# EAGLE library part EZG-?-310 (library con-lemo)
LEMO Connector Source: http://www.lemo.com/pdfs/catalog/ROW/German/unipole_multipole.pdf
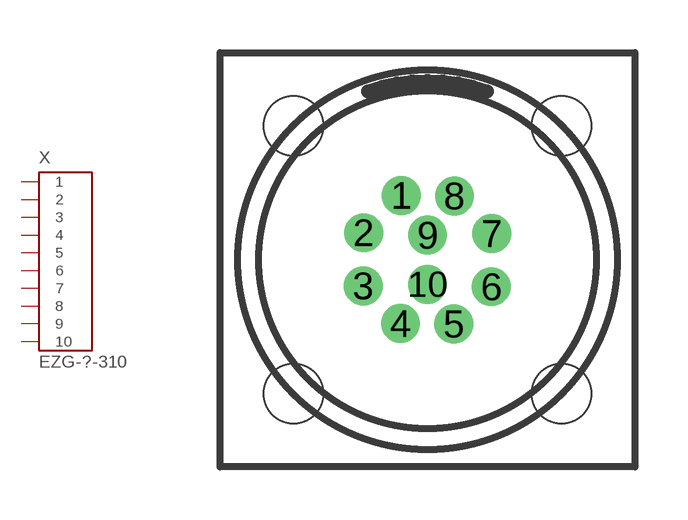
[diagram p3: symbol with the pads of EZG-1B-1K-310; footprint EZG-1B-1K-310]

Designator prefix X

## EZG-1B-310 (OC_FARNELL: unknown; OC_NEWARK: unknown)  [EZG-1B-1K-310]
1  1  pas
2  2  pas
3  3  pas
4  4  pas
5  5  pas
6  6  pas
7  7  pas
8  8  pas
9  9  pas
10  10  pas

## EZG-1K-310 (OC_FARNELL: unknown; OC_NEWARK: unknown)  [EZG-1B-1K-310]
Pads as for EZG-1B-1K-310

## Footprint EZG-1B-1K-310 (pad centres in mm)
LEMO Connector Source: http://www.lemo.com/pdfs/catalog/ROW/German/unipole_multipole.pdf
drill 0.6 pad 1 round: 1 -0.743,1.83; 2 -1.819,0.768; 3 -1.83,-0.743; 4 -0.768,-1.819; 5 0.743,-1.83; 6 1.819,-0.768; 7 1.83,0.743; 8 0.768,1.819; 9 0,0.7; 10 0,-0.7
hole 1.7 at -3.81,3.81
hole 1.7 at 3.81,3.81
hole 1.7 at 3.81,-3.81
hole 1.7 at -3.81,-3.81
